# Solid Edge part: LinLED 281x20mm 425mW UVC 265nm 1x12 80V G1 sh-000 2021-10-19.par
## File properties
Author: radoslaw.kuczynski
Template: iso metric part.par
Last saved by: radoslaw.kuczynski
Revision: 1
Application: Solid Edge
Gęstość: 0.000 kg/m^3
Dokładność: 0.990
Username: radoslaw.kuczynski
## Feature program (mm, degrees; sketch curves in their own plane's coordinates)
body "unnamed Body 1"
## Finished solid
Body 1: solid body, 671 faces, 1864 edges, 1232 vertices.
  Faces by surface: plane 626, cylinder 45
  Edges by curve: line 1774, circle 90
Bounding box of the edges (mm): 281.000 x 4.600 x 19.200, from (-140.5, -3, -9.6) to (140.5, 1.6, 9.6).
Cylindrical faces by radius (mm): R0.5 x24, R0.75 x8, R1.25 x4, R1.5 x2, R1.7 x7
Planar faces by outward normal: +x 98, +y 29, +z 113, -x 98, -y 85, -z 123, oblique 80
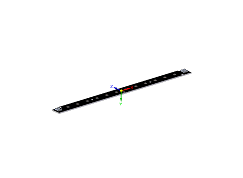
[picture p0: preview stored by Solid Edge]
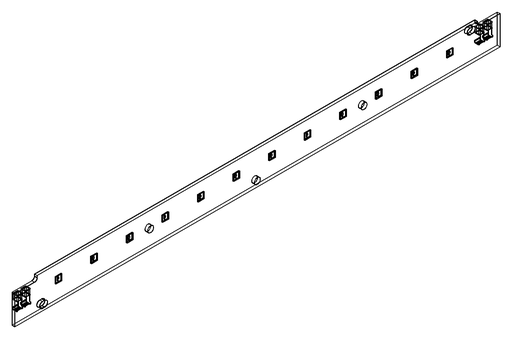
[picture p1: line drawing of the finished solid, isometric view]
